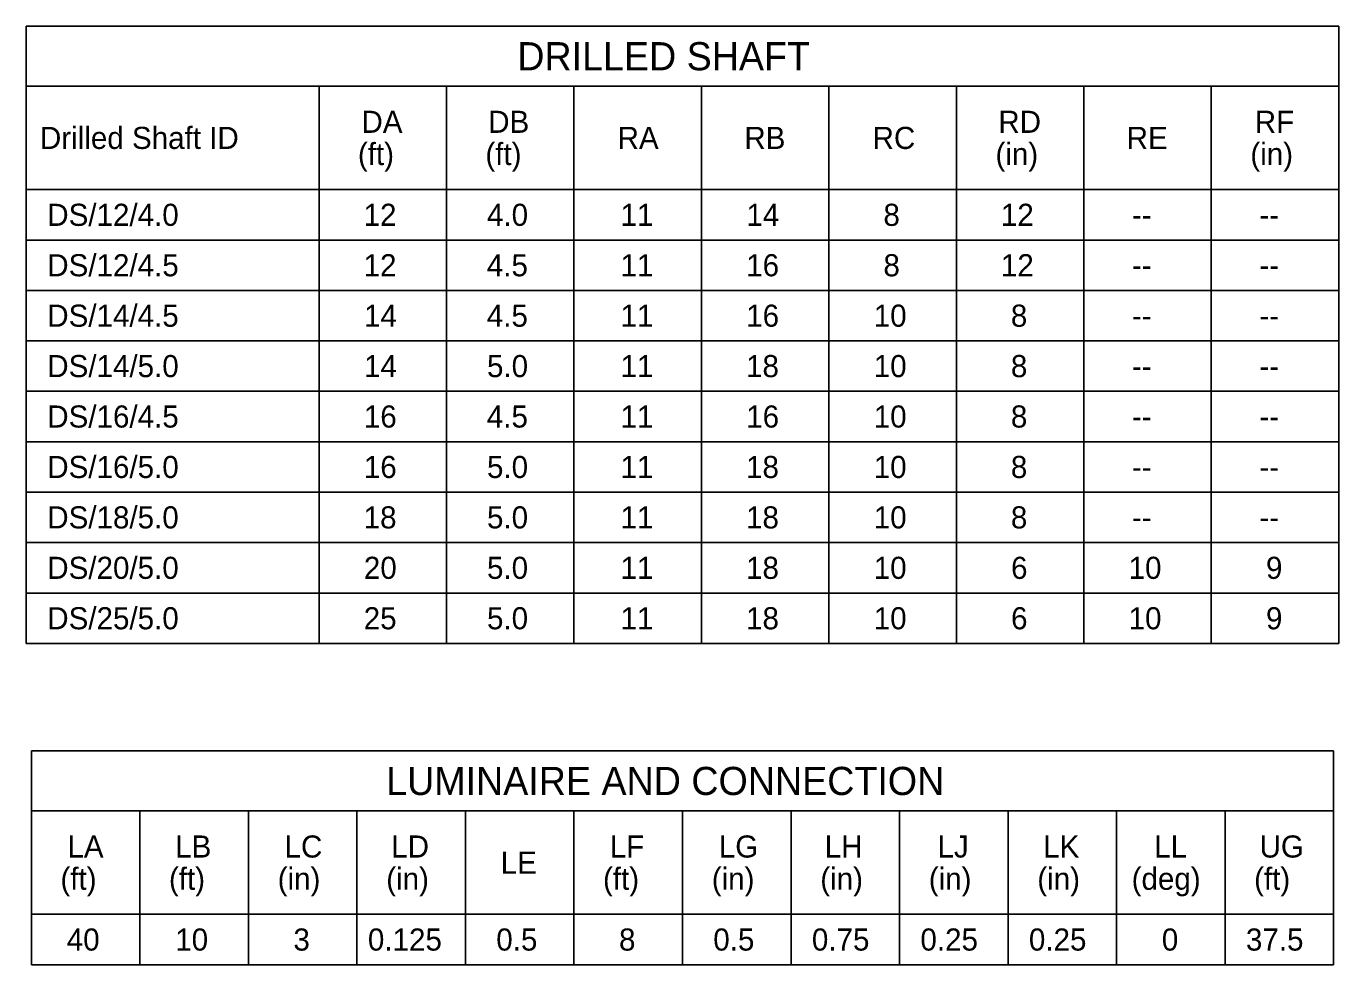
# Model space of a CAD drawing. Extents: x 0.9 to 14.1, y 0.6 to 9.3.
# Drawn here: x 9.983 to 14.14, y 0.619 to 3.59 of the extents above; entities that cross this region are included whole.
import ezdxf

# ---------------------------------------------------------------- set-up
doc = ezdxf.new("R2010")
doc.units = 0
for name, color, linetype in [('SumBoxBorder_dp', 7, 'Continuous'), ('SumBoxLines_dp', 7, 'Continuous'), ('TextLabel', 7, 'Continuous')]:
    doc.layers.add(name, color=color, linetype=linetype)

msp = doc.modelspace()

# ---------------------------------------------------------------- linework, layer by layer
at = {"layer": 'SumBoxBorder_dp'}
for p, q in [((9.9832, 3.5902), (14.1396, 3.5902)), ((9.9832, 3.5902), (9.9832, 1.6364)), ((14.1396, 3.5902), (14.1396, 1.6364)), ((9.9832, 3.4004), (14.1396, 3.4004)), ((9.9832, 3.4004), (14.1396, 3.4004)), ((9.9832, 1.6364), (14.1396, 1.6364)), ((9.9996, 1.296), (14.1232, 1.296)), ((9.9996, 1.296), (9.9996, 0.6193)), ((14.1232, 1.296), (14.1232, 0.6193)), ((9.9996, 1.1062), (14.1232, 1.1062)), ((9.9996, 1.1062), (14.1232, 1.1062)), ((9.9996, 0.6193), (14.1232, 0.6193))]:
    msp.add_line(p, q, dxfattribs=at)
at = {"layer": 'SumBoxLines_dp'}
for p, q in [((10.9105, 3.4004), (10.9105, 1.6364)), ((10.9105, 3.4004), (10.9105, 1.6364)), ((11.3141, 3.4004), (11.3141, 1.6364)), ((11.3141, 3.4004), (11.3141, 1.6364)), ((11.7178, 3.4004), (11.7178, 1.6364)), ((11.7178, 3.4004), (11.7178, 1.6364)), ((12.1214, 3.4004), (12.1214, 1.6364)), ((12.1214, 3.4004), (12.1214, 1.6364)), ((12.525, 3.4004), (12.525, 1.6364)), ((12.525, 3.4004), (12.525, 1.6364)), ((12.9287, 3.4004), (12.9287, 1.6364)), ((12.9287, 3.4004), (12.9287, 1.6364)), ((13.3323, 3.4004), (13.3323, 1.6364)), ((13.3323, 3.4004), (13.3323, 1.6364)), ((13.7359, 3.4004), (13.7359, 1.6364)), ((13.7359, 3.4004), (13.7359, 1.6364)), ((9.9832, 3.0731), (14.1396, 3.0731)), ((9.9832, 3.0731), (14.1396, 3.0731)), ((9.9832, 2.9135), (14.1396, 2.9135)), ((9.9832, 2.9135), (14.1396, 2.9135)), ((9.9832, 2.7538), (14.1396, 2.7538)), ((9.9832, 2.7538), (14.1396, 2.7538)), ((9.9832, 2.5942), (14.1396, 2.5942)), ((9.9832, 2.5942), (14.1396, 2.5942)), ((9.9832, 2.4346), (14.1396, 2.4346)), ((9.9832, 2.4346), (14.1396, 2.4346)), ((9.9832, 2.2749), (14.1396, 2.2749)), ((9.9832, 2.2749), (14.1396, 2.2749)), ((9.9832, 2.1153), (14.1396, 2.1153)), ((9.9832, 2.1153), (14.1396, 2.1153)), ((9.9832, 1.9557), (14.1396, 1.9557)), ((9.9832, 1.9557), (14.1396, 1.9557)), ((9.9832, 1.796), (14.1396, 1.796)), ((10.3432, 1.1062), (10.3432, 0.6193)), ((10.3432, 1.1062), (10.3432, 0.6193)), ((10.6869, 1.1062), (10.6869, 0.6193)), ((10.6869, 1.1062), (10.6869, 0.6193)), ((11.0305, 1.1062), (11.0305, 0.6193)), ((11.0305, 1.1062), (11.0305, 0.6193)), ((11.3741, 1.1062), (11.3741, 0.6193)), ((11.3741, 1.1062), (11.3741, 0.6193)), ((11.7178, 1.1062), (11.7178, 0.6193)), ((11.7178, 1.1062), (11.7178, 0.6193)), ((12.0614, 1.1062), (12.0614, 0.6193)), ((12.0614, 1.1062), (12.0614, 0.6193)), ((12.405, 1.1062), (12.405, 0.6193)), ((12.405, 1.1062), (12.405, 0.6193)), ((12.7487, 1.1062), (12.7487, 0.6193)), ((12.7487, 1.1062), (12.7487, 0.6193)), ((13.0923, 1.1062), (13.0923, 0.6193)), ((13.0923, 1.1062), (13.0923, 0.6193)), ((13.4359, 1.1062), (13.4359, 0.6193)), ((13.4359, 1.1062), (13.4359, 0.6193)), ((13.7796, 1.1062), (13.7796, 0.6193)), ((13.7796, 1.1062), (13.7796, 0.6193)), ((9.9996, 0.7789), (14.1232, 0.7789)), ((9.9996, 0.7789), (14.1232, 0.7789))]:
    msp.add_line(p, q, dxfattribs=at)

# ---------------------------------------------------------------- texts
at = {"layer": 'TextLabel'}
for s, height, p in [('DRILLED SHAFT', 0.089091, (11.5383, 3.4508)), ('DA', 0.07, (11.0447, 3.2528)), ('DB', 0.07, (11.4461, 3.2528)), ('RD', 0.07, (13.0616, 3.2528)), ('RF', 0.07, (13.8736, 3.2528)), ('Drilled Shaft ID', 0.07, (10.0267, 3.2018)), ('RA', 0.07, (11.8559, 3.2018)), ('RB', 0.07, (12.2573, 3.2018)), ('RC', 0.07, (12.6634, 3.2018)), ('RE', 0.07, (13.4679, 3.2018)), ('(ft)', 0.07, (11.0335, 3.1508)), ('(ft)', 0.07, (11.4372, 3.1508)), ('(in)', 0.07, (13.0525, 3.1508)), ('(in)', 0.07, (13.8597, 3.1508)), ('  DS/12/4.0', 0.07, (9.9978, 2.9583)), ('12', 0.07, (11.0515, 2.9583)), ('4.0', 0.07, (11.4423, 2.9583)), ('11', 0.07, (11.8651, 2.9583)), ('14', 0.07, (12.2638, 2.9583)), ('8', 0.07, (12.6977, 2.9583)), ('12', 0.07, (13.0697, 2.9583)), ('--', 0.07, (13.4846, 2.9583)), ('--', 0.07, (13.8882, 2.9583)), ('  DS/12/4.5', 0.07, (9.9978, 2.7987)), ('12', 0.07, (11.0515, 2.7987)), ('4.5', 0.07, (11.4417, 2.7987)), ('11', 0.07, (11.8651, 2.7987)), ('16', 0.07, (12.2632, 2.7987)), ('8', 0.07, (12.6977, 2.7987)), ('12', 0.07, (13.0697, 2.7987)), ('--', 0.07, (13.4846, 2.7987)), ('--', 0.07, (13.8882, 2.7987)), ('  DS/14/4.5', 0.07, (9.9978, 2.639)), ('14', 0.07, (11.0529, 2.639)), ('4.5', 0.07, (11.4417, 2.639)), ('11', 0.07, (11.8651, 2.639)), ('16', 0.07, (12.2632, 2.639)), ('10', 0.07, (12.667, 2.639)), ('8', 0.07, (13.1013, 2.639)), ('--', 0.07, (13.4846, 2.639)), ('--', 0.07, (13.8882, 2.639)), ('  DS/14/5.0', 0.07, (9.9978, 2.4794)), ('14', 0.07, (11.0529, 2.4794)), ('5.0', 0.07, (11.4423, 2.4794)), ('11', 0.07, (11.8651, 2.4794)), ('18', 0.07, (12.2626, 2.4794)), ('10', 0.07, (12.667, 2.4794)), ('8', 0.07, (13.1013, 2.4794)), ('--', 0.07, (13.4846, 2.4794)), ('--', 0.07, (13.8882, 2.4794)), ('  DS/16/4.5', 0.07, (9.9978, 2.3198)), ('16', 0.07, (11.0523, 2.3198)), ('4.5', 0.07, (11.4417, 2.3198)), ('11', 0.07, (11.8651, 2.3198)), ('16', 0.07, (12.2632, 2.3198)), ('10', 0.07, (12.667, 2.3198)), ('8', 0.07, (13.1013, 2.3198)), ('--', 0.07, (13.4846, 2.3198)), ('--', 0.07, (13.8882, 2.3198)), ('  DS/16/5.0', 0.07, (9.9978, 2.1601)), ('16', 0.07, (11.0523, 2.1601)), ('5.0', 0.07, (11.4423, 2.1601)), ('11', 0.07, (11.8651, 2.1601)), ('18', 0.07, (12.2626, 2.1601)), ('10', 0.07, (12.667, 2.1601)), ('8', 0.07, (13.1013, 2.1601)), ('--', 0.07, (13.4846, 2.1601)), ('--', 0.07, (13.8882, 2.1601)), ('  DS/18/5.0', 0.07, (9.9978, 2.0005)), ('18', 0.07, (11.0517, 2.0005)), ('5.0', 0.07, (11.4423, 2.0005)), ('11', 0.07, (11.8651, 2.0005)), ('18', 0.07, (12.2626, 2.0005)), ('10', 0.07, (12.667, 2.0005)), ('8', 0.07, (13.1013, 2.0005)), ('--', 0.07, (13.4846, 2.0005)), ('--', 0.07, (13.8882, 2.0005)), ('  DS/20/5.0', 0.07, (9.9978, 1.8408)), ('20', 0.07, (11.0524, 1.8408)), ('5.0', 0.07, (11.4423, 1.8408)), ('11', 0.07, (11.8651, 1.8408)), ('18', 0.07, (12.2626, 1.8408)), ('10', 0.07, (12.667, 1.8408)), ('6', 0.07, (13.1019, 1.8408)), ('10', 0.07, (13.4742, 1.8408)), ('9', 0.07, (13.9092, 1.8408)), ('  DS/25/5.0', 0.07, (9.9978, 1.6812)), ('25', 0.07, (11.0518, 1.6812)), ('5.0', 0.07, (11.4423, 1.6812)), ('11', 0.07, (11.8651, 1.6812)), ('18', 0.07, (12.2626, 1.6812)), ('10', 0.07, (12.667, 1.6812)), ('6', 0.07, (13.1019, 1.6812)), ('10', 0.07, (13.4742, 1.6812)), ('9', 0.07, (13.9092, 1.6812)), ('LUMINAIRE AND CONNECTION', 0.089091, (11.123, 1.1566)), ('LA', 0.07, (10.1136, 0.9586)), ('LB', 0.07, (10.4549, 0.9586)), ('LC', 0.07, (10.8012, 0.9586)), ('LD', 0.07, (11.1391, 0.9586)), ('LF', 0.07, (11.8313, 0.9586)), ('LG', 0.07, (12.1764, 0.9586)), ('LH', 0.07, (12.5118, 0.9586)), ('LJ', 0.07, (12.869, 0.9586)), ('LK', 0.07, (13.2036, 0.9586)), ('LL', 0.07, (13.5553, 0.9586)), ('UG', 0.07, (13.8888, 0.9586)), ('LE', 0.07, (11.4856, 0.9076)), ('(ft)', 0.07, (10.0915, 0.8566)), ('(ft)', 0.07, (10.4351, 0.8566)), ('(in)', 0.07, (10.7795, 0.8566)), ('(in)', 0.07, (11.1232, 0.8566)), ('(ft)', 0.07, (11.8097, 0.8566)), ('(in)', 0.07, (12.1541, 0.8566)), ('(in)', 0.07, (12.4977, 0.8566)), ('(in)', 0.07, (12.8413, 0.8566)), ('(in)', 0.07, (13.185, 0.8566)), ('(deg)', 0.07, (13.4837, 0.8566)), ('(ft)', 0.07, (13.8715, 0.8566)), ('40', 0.07, (10.1115, 0.6641)), ('10', 0.07, (10.4551, 0.6641)), ('3', 0.07, (10.8293, 0.6641)), ('0.125', 0.07, (11.0652, 0.6641)), ('0.5', 0.07, (11.4717, 0.6641)), ('8', 0.07, (11.8604, 0.6641)), ('0.5', 0.07, (12.1589, 0.6641)), ('0.75', 0.07, (12.4712, 0.6641)), ('0.25', 0.07, (12.8148, 0.6641)), ('0.25', 0.07, (13.1584, 0.6641)), ('0', 0.07, (13.5793, 0.6641)), ('37.5', 0.07, (13.8457, 0.6641))]:
    msp.add_text(s, height=height, dxfattribs=at).set_placement(p)

doc.saveas('drawing.dxf')
